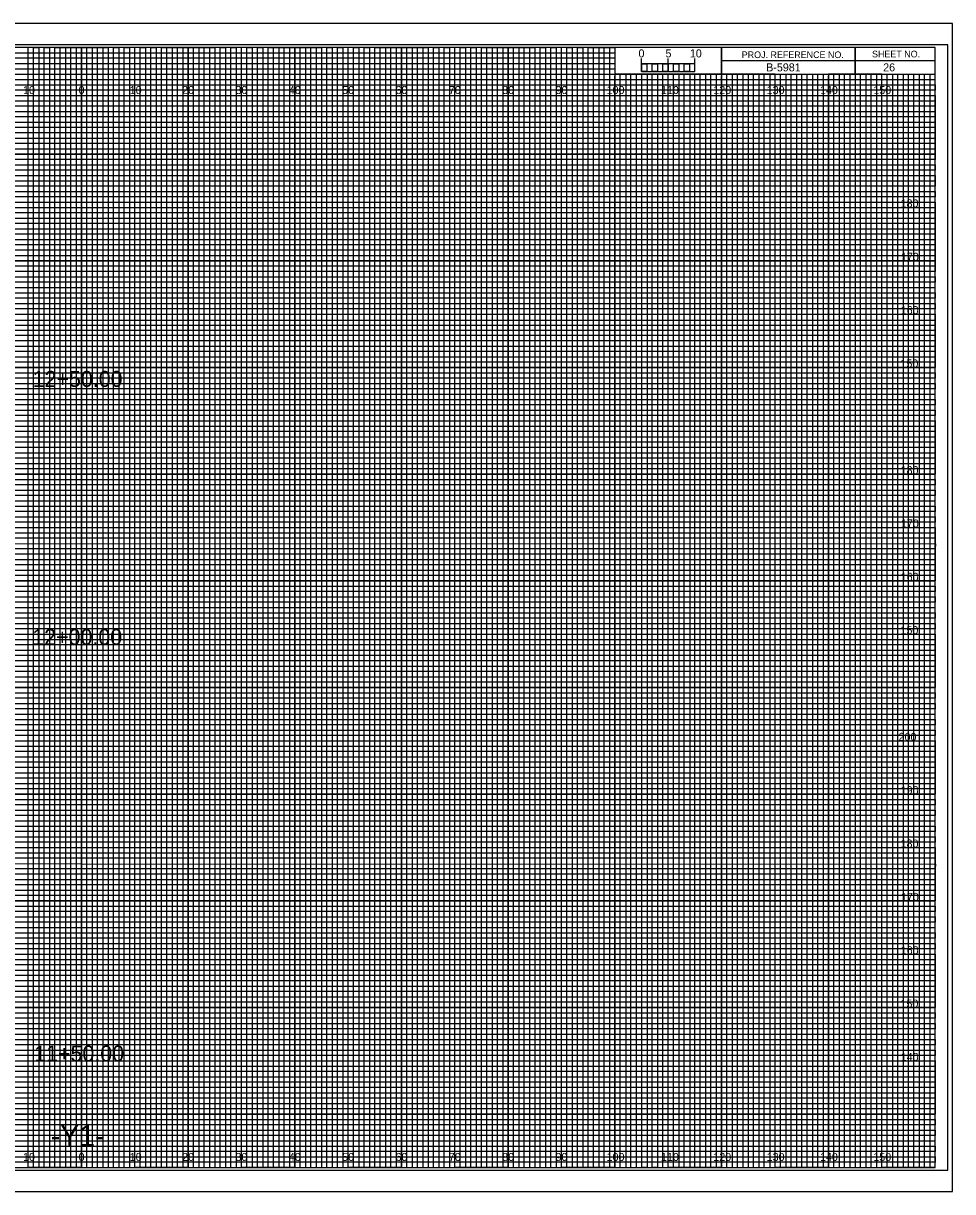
# Model space of a CAD drawing. Extents: x -13 to 323, y -5 to 654.
# Drawn here: x 149.1 to 323.3, y 215.5 to 434.5 of the extents above; entities that cross this region are included whole.
import ezdxf

# ---------------------------------------------------------------- set-up
doc = ezdxf.new("R2010")
doc.units = 0
for name, color, linetype in [('Exist Cross Section Cell', 7, 'Continuous'), ('Exist XS Center Line Elevation Label', 7, 'Continuous'), ('Exist XS Ground Line', 7, 'Continuous'), ('Prop CMT Concrete Structures', 7, 'Continuous'), ('Prop CMT Guardrail Graphics', 7, 'Continuous'), ('Prop CMT Pvmt Course 1', 7, 'Continuous'), ('Prop CMT Pvmt Course 2', 7, 'Continuous'), ('Prop CMT Pvmt Course 3', 7, 'Continuous'), ('Prop CMT Pvmt Surface', 7, 'Continuous'), ('Prop CMT Shld Paved Course 1', 7, 'Continuous'), ('Prop CMT Shld Paved Course 2', 7, 'Continuous'), ('Prop CMT Shld Paved Course 3', 7, 'Continuous'), ('Prop CMT Subgrade Earthwork', 7, 'Continuous'), ('Prop XS Ditch Standard Text', 7, 'Continuous'), ('Prop XS SE Text', 7, 'Continuous'), ('Prop XS Side Slope Text', 7, 'Continuous'), ('Scratch_Level_0', 7, 'Continuous')]:
    doc.layers.add(name, color=color, linetype=linetype)

msp = doc.modelspace()

# ---------------------------------------------------------------- linework, layer by layer
at = {"layer": 'Exist XS Center Line Elevation Label'}
for points in [[(145, 220), (155, 220), (155, 430), (165, 430), (165, 220), (175, 220), (175, 430), (185, 430), (185, 220), (195, 220), (195, 430), (205, 430), (205, 220), (215, 220), (215, 430), (225, 430), (225, 220), (235, 220), (235, 430), (245, 430), (245, 220), (255, 220), (255, 430), (259.93, 430), (260, 430), (260, 425), (264.99, 425), (264.99, 220), (275, 220), (275, 425), (285, 425), (285, 220), (295, 220), (295, 425), (305, 425), (305, 220), (315, 220), (315, 425)], [(0, 425), (275, 425)], [(0, 405), (320, 405), (320, 415), (0, 415)], [(0, 385), (320, 385), (320, 395), (0, 395)], [(0, 365), (320, 365), (320, 375), (0, 375)], [(0, 345), (320, 345), (320, 355), (0, 355)], [(0, 325), (320, 325), (320, 335), (0, 335)], [(0, 305), (320, 305), (320, 315), (0, 315)], [(0, 285), (320, 285), (320, 295), (0, 295)], [(0, 265), (320, 265), (320, 275), (0, 275)], [(0, 245), (320, 245), (320, 255), (0, 255)], [(0, 225), (320, 225), (320, 235), (0, 235)]]:
    msp.add_lwpolyline(points, dxfattribs=at)
at = {"layer": 'Exist XS Ground Line'}
for p, q in [((150, 430), (140, 430)), ((150, 220), (150, 430)), ((170, 430), (160, 430)), ((160, 430), (160, 220)), ((170, 220), (170, 430)), ((190, 430), (180, 430)), ((180, 430), (180, 220)), ((190, 220), (190, 430)), ((210, 430), (200, 430)), ((200, 430), (200, 220)), ((210, 220), (210, 430)), ((230, 430), (220, 430)), ((220, 430), (220, 220)), ((230, 220), (230, 430)), ((250, 430), (240, 430)), ((240, 430), (240, 220)), ((250, 220), (250, 430)), ((260, 430), (260, 220)), ((270, 220), (270, 425)), ((290, 425), (280, 425)), ((280, 425), (280, 220)), ((290, 220), (290, 425)), ((310, 425), (300, 425)), ((300, 425), (300, 220)), ((310, 220), (310, 425)), ((160, 220), (150, 220)), ((180, 220), (170, 220)), ((200, 220), (190, 220)), ((220, 220), (210, 220)), ((240, 220), (230, 220)), ((260, 220), (250, 220)), ((280, 220), (270, 220)), ((300, 220), (290, 220)), ((320, 220), (310, 220)), ((320, 220), (320, 220))]:
    msp.add_line(p, q, dxfattribs=at)
for points in [[(0, 420), (320, 420), (320, 410), (0, 410)], [(0, 400), (320, 400), (320, 390), (0, 390)], [(0, 380), (320, 380), (320, 370), (0, 370)], [(0, 360), (320, 360), (320, 350), (0, 350)], [(0, 340), (320, 340), (320, 330), (0, 330)], [(0, 320), (320, 320), (320, 310), (0, 310)], [(0, 300), (320, 300), (320, 290), (0, 290)], [(0, 280), (320, 280), (320, 270), (0, 270)], [(0, 260), (320, 260), (320, 250), (0, 250)], [(0, 240), (320, 240), (320, 230), (0, 230)]]:
    msp.add_lwpolyline(points, dxfattribs=at)
at = {"layer": 'Prop CMT Pvmt Course 1'}
for p, q in [((323.3, 434.5), (-13.4, 434.5)), ((-13.4, 215.5), (323.3, 215.5))]:
    msp.add_line(p, q, dxfattribs=at)
at = {"layer": 'Prop CMT Pvmt Course 2'}
msp.add_lwpolyline([(-13.4, 215.5), (323.3, 215.5), (323.3, 434.5), (-13.4, 434.5)], close=True, dxfattribs=at)
at = {"layer": 'Prop CMT Pvmt Course 3'}
msp.add_lwpolyline([(-10.8, 219.5), (322.4, 219.5), (322.4, 430.5), (-10.8, 430.5)], close=True, dxfattribs=at)
at = {"layer": 'Prop CMT Shld Paved Course 1'}
for p, q in [((305, 430), (305, 425)), ((305, 425), (305, 430)), ((280, 427.5), (280, 425)), ((320, 427.49), (280, 427.49)), ((280, 425), (320, 425))]:
    msp.add_line(p, q, dxfattribs=at)
for points in [[(320, 430), (0, 430), (0, 220), (320, 220)], [(280, 430), (260, 430), (260, 425.03), (280, 425.03)], [(320, 430), (280, 430), (280, 425), (320, 425)]]:
    msp.add_lwpolyline(points, close=True, dxfattribs=at)
at = {"layer": 'Prop CMT Shld Paved Course 2'}
for p, q in [((267, 425), (266.01, 425)), ((266.01, 425), (266.01, 220)), ((267, 220), (267, 425)), ((269, 425), (268, 425)), ((268, 425), (268, 220)), ((269, 220), (269, 425)), ((266.01, 220), (265, 220)), ((268, 220), (267, 220))]:
    msp.add_line(p, q, dxfattribs=at)
for points in [[(150, 220), (151, 220), (151, 430), (152, 430), (152, 220)], [(152, 220), (153, 220), (153, 430), (154, 430), (154, 220)], [(155, 220), (156, 220), (156, 430), (157, 430), (157, 220)], [(157, 220), (158, 220), (158, 430), (159, 430), (159, 220)], [(160, 220), (161, 220), (161, 430), (162, 430), (162, 220)], [(162, 220), (163, 220), (163, 430), (164, 430), (164, 220)], [(165, 220), (166, 220), (166, 430), (167, 430), (167, 220)], [(167, 220), (168, 220), (168, 430), (169, 430), (169, 220)], [(170, 220), (171, 220), (171, 430), (172, 430), (172, 220)], [(172, 220), (173, 220), (173, 430), (174, 430), (174, 220)], [(175, 220), (176, 220), (176, 430), (177, 430), (177, 220)], [(177, 220), (178, 220), (178, 430), (179, 430), (179, 220)], [(180, 220), (181, 220), (181, 430), (182, 430), (182, 220)], [(182, 220), (183, 220), (183, 430), (184, 430), (184, 220)], [(185, 220), (186, 220), (186, 430), (187, 430), (187, 220)], [(187, 220), (188, 220), (188, 430), (189, 430), (189, 220)], [(190, 220), (191, 220), (191, 430), (192, 430), (192, 220)], [(192, 220), (193, 220), (193, 430), (194, 430), (194, 220)], [(195, 220), (196, 220), (196, 430), (197, 430), (197, 220)], [(197, 220), (198, 220), (198, 430), (199, 430), (199, 220)], [(200, 220), (201, 220), (201, 430), (202, 430), (202, 220)], [(202, 220), (203, 220), (203, 430), (204, 430), (204, 220)], [(205, 220), (206, 220), (206, 430), (207, 430), (207, 220)], [(207, 220), (208, 220), (208, 430), (209, 430), (209, 220)], [(210, 220), (211, 220), (211, 430), (212, 430), (212, 220)], [(212, 220), (213, 220), (213, 430), (214, 430), (214, 220)], [(215, 220), (216, 220), (216, 430), (217, 430), (217, 220)], [(217, 220), (218, 220), (218, 430), (219, 430), (219, 220)], [(220, 220), (221, 220), (221, 430), (222, 430), (222, 220)], [(222, 220), (223, 220), (223, 430), (224, 430), (224, 220)], [(225, 220), (226, 220), (226, 430), (227, 430), (227, 220)], [(227, 220), (228, 220), (228, 430), (229, 430), (229, 220)], [(230, 220), (231, 220), (231, 430), (232, 430), (232, 220)], [(232, 220), (233, 220), (233, 430), (234, 430), (234, 220)], [(235, 220), (236, 220), (236, 430), (237, 430), (237, 220)], [(237, 220), (238, 220), (238, 430), (239, 430), (239, 220)], [(240, 220), (241, 220), (241, 430), (242, 430), (242, 220)], [(242, 220), (243, 220), (243, 430), (244, 430), (244, 220)], [(245, 220), (246, 220), (246, 430), (247, 430), (247, 220)], [(247, 220), (248, 220), (248, 430), (249, 430), (249, 220)], [(250, 220), (251, 220), (251, 430), (252, 430), (252, 220)], [(252, 220), (253, 220), (253, 430), (254, 430), (254, 220)], [(255, 220), (256, 220), (256, 430), (257, 430), (257, 220)], [(257, 220), (258, 220), (258, 430), (259, 430), (259, 220)], [(260, 220), (261, 220), (261, 425), (262.02, 425), (262.02, 220)], [(262, 220), (263, 220), (263, 425), (263.99, 425), (263.99, 220)], [(270, 220), (270.98, 220), (270.98, 425), (272, 425), (272, 220)], [(272, 220), (273, 220), (273, 425), (274.05, 425), (274.05, 220)], [(275, 220), (276, 220), (276, 425), (277, 425), (277, 220)], [(277, 220), (278, 220), (278, 425), (279, 425), (279, 220)], [(280, 220), (281, 220), (281, 425), (282, 425), (282, 220)], [(282, 220), (283, 220), (283, 425), (284, 425), (284, 220)], [(285, 220), (286, 220), (286, 425), (287, 425), (287, 220)], [(287, 220), (288, 220), (288, 425), (289, 425), (289, 220)], [(290, 220), (291, 220), (291, 425), (292, 425), (292, 220)], [(292, 220), (293, 220), (293, 425), (294, 425), (294, 220)], [(295, 220), (296, 220), (296, 425), (297, 425), (297, 220)], [(297, 220), (298, 220), (298, 425), (299, 425), (299, 220)], [(300, 220), (301, 220), (301, 425), (302, 425), (302, 220)], [(302, 220), (303, 220), (303, 425), (304, 425), (304, 220)], [(305, 220), (306, 220), (306, 425), (307, 425), (307, 220)], [(307, 220), (308, 220), (308, 425), (309, 425), (309, 220)], [(310, 220), (311, 220), (311, 425), (312, 425), (312, 220)], [(312, 220), (313, 220), (313, 425), (314, 425), (314, 220)], [(315, 220), (316, 220), (316, 425), (317, 425), (317, 220)], [(317, 220), (318, 220), (318, 425), (319, 425), (319, 220)]]:
    msp.add_lwpolyline(points, dxfattribs=at)
at = {"layer": 'Prop CMT Shld Paved Course 3'}
for p, q in [((265, 425.49), (265, 427.9)), ((265, 426.9), (265, 427.9)), ((270, 425.49), (270, 427.9)), ((275, 425.49), (275, 427.9)), ((275, 426.9), (275, 427.9))]:
    msp.add_line(p, q, dxfattribs=at)
for points in [[(275, 426.9), (265, 426.9), (265, 425.49), (275, 425.49)], [(265, 426.9), (266, 426.9), (266, 425.49), (265, 425.49)], [(267, 426.9), (268, 426.9), (268, 425.49), (267, 425.49)], [(269, 426.9), (270, 426.9), (270, 425.49), (269, 425.49)], [(271, 426.9), (272, 426.9), (272, 425.49), (271, 425.49)], [(273, 426.9), (274, 426.9), (274, 425.49), (273, 425.49)]]:
    msp.add_lwpolyline(points, close=True, dxfattribs=at)
at = {"layer": 'Prop CMT Subgrade Earthwork'}
for p, q in [((150, 220), (150, 430)), ((160, 220), (160, 430)), ((170, 220), (170, 430)), ((180, 220), (180, 430)), ((190, 220), (190, 430)), ((200, 220), (200, 430)), ((210, 220), (210, 430)), ((220, 220), (220, 430)), ((230, 220), (230, 430)), ((240, 220), (240, 430)), ((250, 220), (250, 430)), ((260, 220), (260, 424.69)), ((270, 220), (270, 424.69)), ((280, 220), (280, 424.69)), ((290, 220), (290, 424.69)), ((300, 220), (300, 424.69)), ((310, 220), (310, 424.69)), ((0, 420), (320, 420)), ((0, 410), (320, 410)), ((0, 400), (320, 400)), ((0, 390), (320, 390)), ((0, 380), (320, 380)), ((0, 370), (320, 370)), ((0, 360), (320, 360)), ((0, 350), (320, 350)), ((0, 340), (320, 340)), ((0, 330), (320, 330)), ((0, 320), (320, 320)), ((0, 310), (320, 310)), ((0, 300), (320, 300)), ((0, 290), (320, 290)), ((0, 280), (320, 280)), ((0, 270), (320, 270)), ((0, 260), (320, 260)), ((0, 250), (320, 250)), ((0, 240), (320, 240)), ((0, 230), (320, 230))]:
    msp.add_line(p, q, dxfattribs=at)
at = {"layer": 'Scratch_Level_0'}
for p, q in [((0, 429), (260, 429)), ((260, 427.98), (0, 427.98)), ((260, 429), (260, 427.98)), ((0, 427), (260, 427)), ((260, 425.89), (0, 425.89)), ((260, 427), (260, 425.89)), ((0, 424), (320, 424))]:
    msp.add_line(p, q, dxfattribs=at)
for points in [[(0, 423), (270, 423), (320, 423), (320, 422), (0, 422)], [(0, 421), (320, 421), (320, 419), (0, 419)], [(0, 418), (320, 418), (320, 417), (0, 416.98)], [(0, 416), (320, 416), (320, 414), (0, 414)], [(0, 413), (320, 413), (320, 412), (0, 412)], [(0, 411), (320, 411), (320, 409), (0, 409)], [(0, 408), (320, 408), (320, 407), (0, 407)], [(0, 406), (320, 406), (320, 404), (0, 404)], [(0, 403), (320, 403), (320, 402), (0, 402)], [(0, 401), (320, 401), (320, 399), (0, 399)], [(0, 398), (320, 398), (320, 397), (0, 397)], [(0, 396), (320, 396), (320, 393.95), (320, 393), (320, 392), (0, 392)], [(0, 394), (320, 394), (320, 393), (0, 393)], [(0, 391), (320, 391), (320, 389), (0, 389.03)], [(0, 389.03), (320, 389), (320, 388), (0, 388)], [(0, 387), (320, 387), (320, 386), (0, 386)], [(0, 384), (320, 384), (320, 383), (0, 383)], [(0, 382), (320, 382), (320, 381), (0, 381)], [(-0.07, 378.89), (320, 378.89), (320, 377.88), (-0.07, 377.88)], [(0, 377), (320, 377), (320, 376), (0, 376)], [(0, 374), (320, 374), (320, 373), (0, 373)], [(0, 372), (320, 372), (320, 371), (0, 371)], [(0, 369), (320, 369), (320, 368), (0, 368)], [(0, 367), (320, 367), (320, 366), (0, 366)], [(0, 364), (320, 364), (320, 363), (0, 363)], [(0, 362), (320, 362), (320, 361), (0, 361)], [(0, 359), (320, 359), (319.99, 357.98), (0, 358)], [(0, 357), (320, 357), (320, 356), (0, 356)], [(0, 354), (320, 354), (320, 353), (0, 353)], [(0, 352), (320, 352), (320, 351), (0, 351)], [(0, 349), (320, 349), (320, 348), (0, 348)], [(0, 347), (320, 347), (320, 346), (0, 346)], [(0, 344), (320, 344), (320, 343), (0, 343)], [(0, 342), (320, 342), (320, 341), (0, 341)], [(0, 339), (320, 339), (320, 338), (0, 338)], [(0, 336.99), (320.07, 336.91), (320, 336), (0, 336)], [(0, 334), (320, 334), (320, 333), (0, 333)], [(0, 332), (320, 332), (320, 331), (0, 331)], [(0, 329), (320, 329), (320, 328), (0, 328)], [(0, 327), (320, 327), (320, 326), (0, 326)], [(0, 324), (320, 324), (320, 323), (0, 323)], [(0, 322), (320, 322), (320, 321), (0, 321)], [(0, 319), (320, 319), (320, 318), (0, 318)], [(0, 317), (320, 317), (320, 316), (0, 316)], [(0, 314), (320, 314), (320, 313), (0, 313)], [(0, 312), (320, 312), (320, 311), (0, 311)], [(0, 309), (320, 309), (320, 308), (0, 308)], [(0, 307), (320, 307), (320, 306), (0, 306)], [(0, 304), (320, 304), (320, 303), (0, 303)], [(0, 302), (320, 302), (320, 301), (0, 301)], [(0, 299), (320, 299), (319.99, 297.98), (0, 298)], [(0, 297), (320, 297), (320, 296), (0, 296)], [(0, 294), (320, 294), (320, 293), (0, 293)], [(0, 292), (320, 292), (320, 291), (0, 291)], [(0, 289), (320, 289), (320, 288), (0, 288)], [(0, 287), (320, 287), (320, 286), (0, 286)], [(0, 284), (320, 284), (320, 283), (0, 283)], [(0, 282), (320, 282), (320, 281), (0, 281)], [(0, 279), (320, 279), (320, 278), (0, 278)], [(0, 276.99), (320.07, 276.91), (320, 276), (0, 276)], [(0, 274), (320, 274), (320, 273), (0, 273)], [(0, 272), (320, 272), (320, 271), (0, 271)], [(0, 269), (320, 269), (320, 268), (0, 268)], [(0, 267), (320, 267), (320, 266), (0, 266)], [(0, 264), (320, 264), (320, 263), (0, 263)], [(0, 262), (320, 262), (320, 261), (0, 261)], [(0, 259), (320, 259), (320, 258), (0, 258)], [(0, 257), (320, 257), (320, 256), (0, 256)], [(0, 254), (320, 254), (320, 253), (0, 253)], [(0, 252), (320, 252), (320, 251), (0, 251)], [(0, 249), (320, 249), (320, 248), (0, 248)], [(0, 247), (320, 247), (320, 246), (0, 246)], [(0, 244), (320, 244), (320, 243), (0, 243)], [(0, 242), (320, 242), (320, 241), (0, 241)], [(0, 239), (320, 239), (320, 238), (0, 238)], [(0, 237), (320, 237), (320, 236), (0, 236)], [(0, 234), (320, 234), (320, 233), (0, 233)], [(0, 232), (320, 232), (320, 231), (0, 231)], [(0, 229), (320, 229), (320, 228), (0, 228)], [(0, 227), (320, 227), (320, 226), (0, 226)], [(0, 224), (320, 224), (320, 223), (0, 223)], [(0, 222), (320, 222), (320, 221), (0, 221)]]:
    msp.add_lwpolyline(points, dxfattribs=at)

# ---------------------------------------------------------------- texts
at = {"layer": 'Exist Cross Section Cell'}
for s, p in [('10', (149.04, 421.25)), ('0', (159.45, 421.25)), ('0', (159.45, 421.25)), ('10', (169.04, 421.25)), ('20', (178.86, 421.25)), ('30', (188.86, 421.25)), ('40', (198.86, 421.25)), ('50', (208.86, 421.25)), ('60', (218.86, 421.25)), ('70', (228.86, 421.25)), ('80', (238.86, 421.25)), ('90', (248.86, 421.25)), ('100', (258.44, 421.25)), ('110', (268.62, 421.25)), ('120', (278.44, 421.25)), ('130', (288.44, 421.25)), ('140', (298.44, 421.25)), ('150', (308.44, 421.25)), ('10', (149.04, 221.25)), ('0', (159.45, 221.25)), ('0', (159.45, 221.25)), ('10', (169.04, 221.25)), ('20', (178.86, 221.25)), ('30', (188.86, 221.25)), ('40', (198.86, 221.25)), ('50', (208.86, 221.25)), ('60', (218.86, 221.25)), ('70', (228.86, 221.25)), ('80', (238.86, 221.25)), ('90', (248.86, 221.25)), ('100', (258.44, 221.25)), ('110', (268.62, 221.25)), ('120', (278.44, 221.25)), ('130', (288.44, 221.25)), ('140', (298.44, 221.25)), ('150', (308.44, 221.25))]:
    msp.add_text(s, height=1.5, dxfattribs=at).set_placement(p)
at = {"layer": 'Prop CMT Concrete Structures'}
for s, p in [('12+50.00', (150.84, 366.35)), ('12+00.00', (150.77, 317.98)), ('11+50.00', (151.13, 239.89))]:
    msp.add_text(s, height=3, dxfattribs=at).set_placement(p)
at = {"layer": 'Prop CMT Guardrail Graphics'}
for s, p in [('180', (313.55, 400)), ('170', (313.61, 390)), ('160', (313.57, 380)), ('150', (313.52, 370)), ('180', (313.55, 350)), ('170', (313.61, 340)), ('160', (313.57, 330)), ('150', (313.52, 320)), ('200', (313.17, 300)), ('190', (313.57, 290)), ('180', (313.55, 280)), ('170', (313.61, 270)), ('160', (313.57, 260)), ('150', (313.52, 250)), ('140', (313.57, 240))]:
    msp.add_text(s, height=1.5, dxfattribs=at).set_placement(p)
at = {"layer": 'Prop CMT Pvmt Surface'}
for s, p in [('5', (269.47, 428.12)), ('10', (274.04, 428.12))]:
    msp.add_text(s, height=1.5, dxfattribs=at).set_placement(p)
at = {"layer": 'Prop CMT Shld Paved Course 1'}
for s, p in [('PROJ. REFERENCE NO.', (283.77, 427.99)), ('SHEET NO.', (308.19, 428.12))]:
    msp.add_text(s, height=1.25, dxfattribs=at).set_placement(p)
at = {"layer": 'Prop CMT Shld Paved Course 3'}
msp.add_text('0', height=1.5, dxfattribs=at).set_placement((264.41, 428.12))
at = {"layer": 'Prop XS Ditch Standard Text'}
msp.add_text('-Y1-', height=4, dxfattribs=at).set_placement((154.21, 224))
at = {"layer": 'Prop XS SE Text'}
msp.add_text(' B-5981', height=1.5, dxfattribs=at).set_placement((287.79, 425.5))
at = {"layer": 'Prop XS Side Slope Text'}
msp.add_text('26', height=1.5, dxfattribs=at).set_placement((310.28, 425.5))

doc.saveas('drawing.dxf')
